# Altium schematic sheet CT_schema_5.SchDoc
size 218 x 258 mm
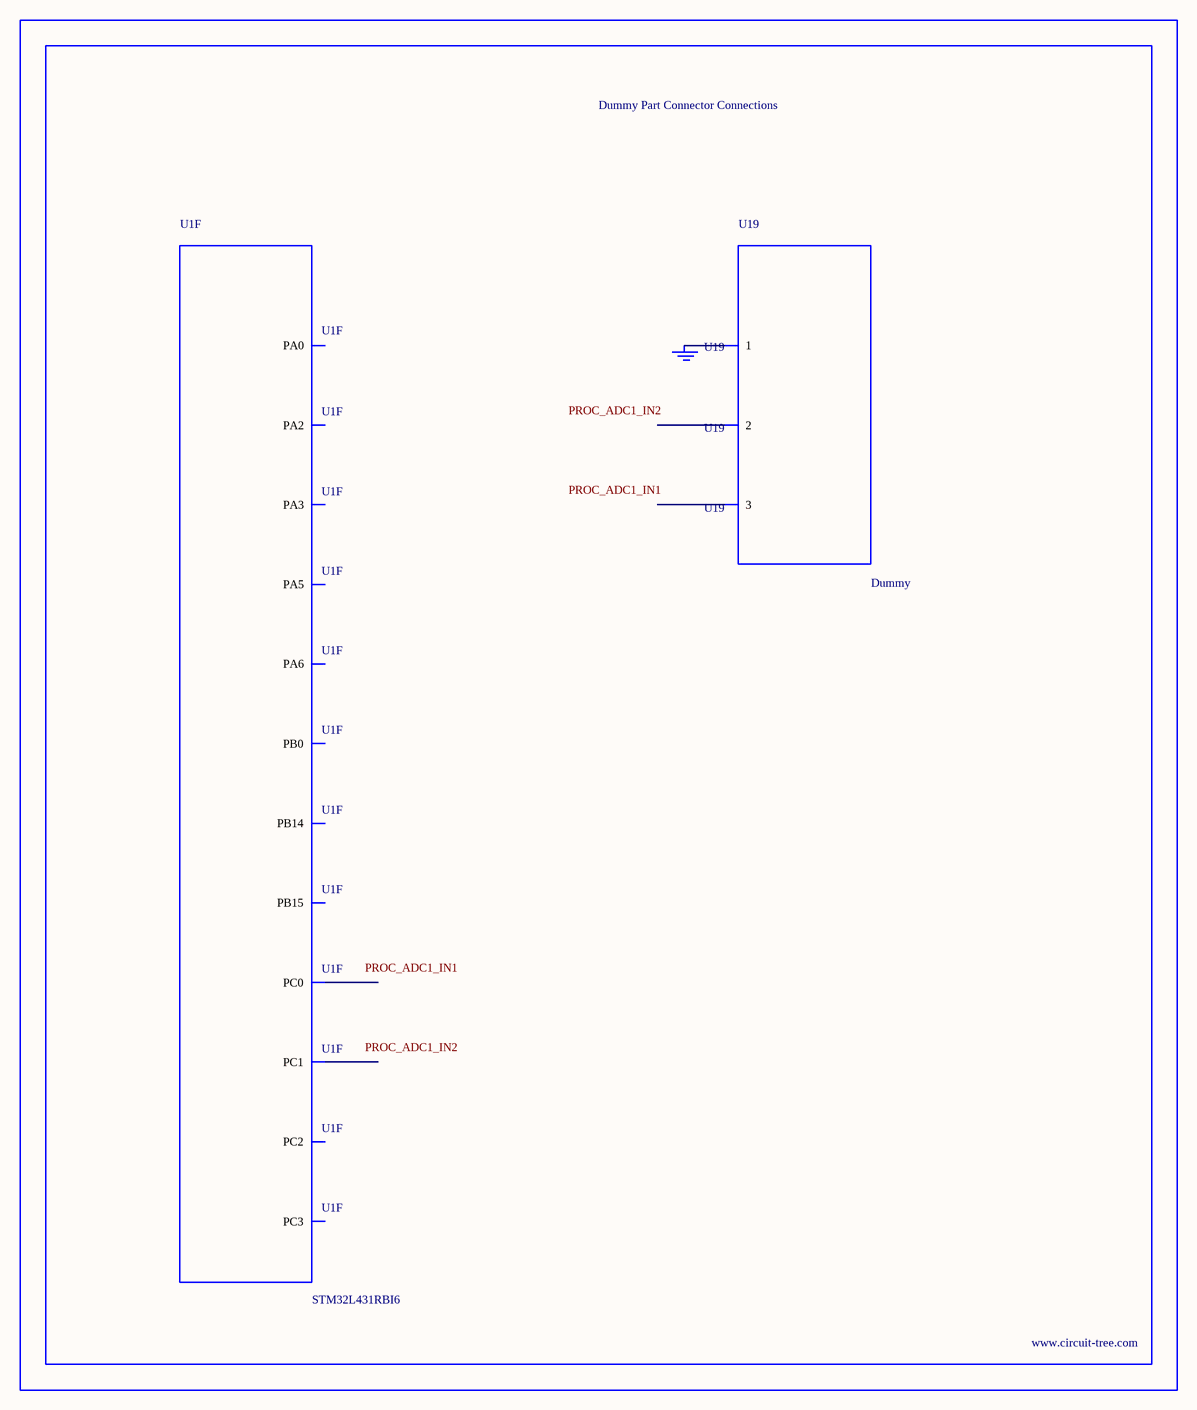
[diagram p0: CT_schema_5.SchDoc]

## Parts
BORDER4  (no value)
GND_INSTANCE_4_0  (no value)
U1  STM32L431RBI6  [UFBGA64]  (part F of 6)
U19  Dummy  [DUMMY_PACKAGE_207]

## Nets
NetGND_INSTANCE_4_0_0: GND_INSTANCE_4_0.0(GND) U19.1

Not connected (* = marked no-connect by the designer): U1 E2(PC1) E3(PC0) F2(PC2) F3(PA2) F4(PA5) F5(PB0) F7(PB15) F8(PB14) G1(PC3) G2(PA0) G3(PA3) G4(PA6); U19 2 3

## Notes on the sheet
- Labels drawn without touching a wire or pin: PROC_ADC1_IN1, PROC_ADC1_IN2

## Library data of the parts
BORDER4 = BORDER_PAGE4
GND_INSTANCE_4_0 = GND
